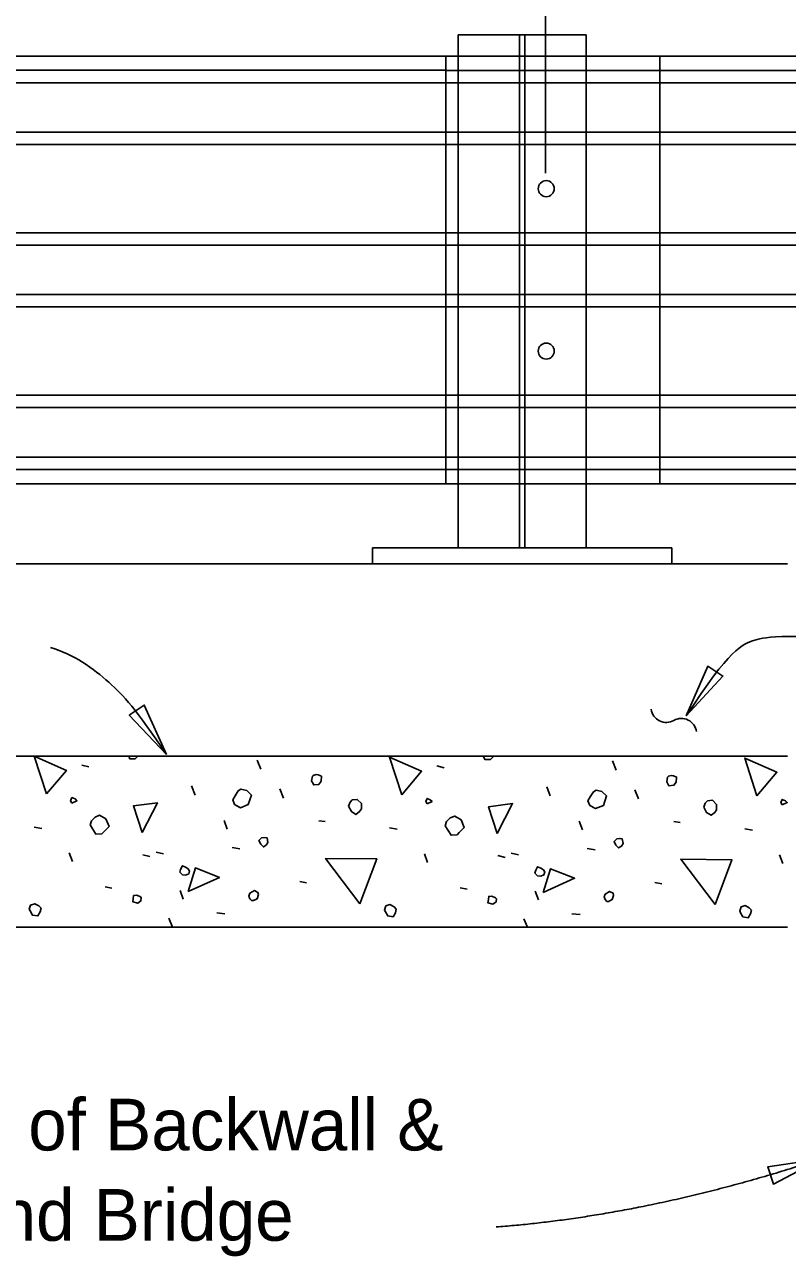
# Model space of a CAD drawing. Extents: x 0 to 41.1, y 0 to 25.9.
# Drawn here: x 24.589 to 27.563, y 5.17 to 9.971 of the extents above; entities that cross this region are included whole.
import ezdxf

# ---------------------------------------------------------------- set-up
doc = ezdxf.new("R2010")
doc.units = 0
for name, color, linetype in [('Dimension', 7, 'Continuous'), ('ExistSuperStruct', 7, 'Continuous'), ('Miscellaneous', 7, 'Continuous'), ('SteelMisc', 7, 'Continuous'), ('SteelMisc_h', 7, 'Continuous')]:
    doc.layers.add(name, color=color, linetype=linetype)

msp = doc.modelspace()

# ---------------------------------------------------------------- linework, layer by layer
at = {"layer": 'Dimension'}
for points in [[(27.168, 7.2761), (27.2522, 7.4698), (27.3113, 7.4313)], [(25.1421, 7.1256), (25.0556, 7.3183), (24.9969, 7.2791)], [(27.6953, 5.5504), (27.4865, 5.5185), (27.5086, 5.4515)]]:
    msp.add_lwpolyline(points, close=True, dxfattribs=at)
for centre, start, end in [((27.0905, 7.3104), 187.9536, 299.6808), ((27.1496, 7.2068), 7.9536, 119.6808)]:
    msp.add_arc(centre, 0.0596, start, end, dxfattribs=at)
for points, degree in [([(28.0581, 7.5636), (27.5366, 7.5973), (27.4332, 7.5751), (27.3392, 7.5386), (27.1681, 7.276)], 3), ([(24.6899, 7.5424), (24.7811, 7.5179), (24.9336, 7.4026), (25.0214, 7.3059), (25.1421, 7.1255)], 3), ([(27.6953, 5.5504), (27.0315, 5.3308), (26.4276, 5.2844)], 2)]:
    msp.add_open_spline(points, degree=degree, dxfattribs=at)
at = {"layer": 'ExistSuperStruct'}
for p, q in [((19.779, 7.8689), (27.5627, 7.8689)), ((27.5627, 7.1189), (19.779, 7.1189)), ((19.779, 6.4523), (27.5627, 6.4523))]:
    msp.add_line(p, q, dxfattribs=at)
at = {"layer": 'Miscellaneous'}
for p, q in [((26.6203, 9.392), (26.6203, 13.4579)), ((26.2319, 9.848), (26.2319, 8.1814)), ((27.0652, 9.848), (27.0652, 8.1814)), ((26.2319, 9.7925), (37.5468, 9.7925)), ((26.2319, 9.7443), (37.5468, 9.7443)), ((26.2319, 9.5515), (37.5468, 9.5515)), ((26.2319, 9.5032), (37.5468, 9.5032)), ((26.2319, 9.1593), (37.5468, 9.1593)), ((26.2319, 9.1111), (37.5468, 9.1111)), ((26.2319, 8.9182), (37.5468, 8.9182)), ((26.2319, 8.8701), (37.5468, 8.8701)), ((26.2319, 8.5262), (37.5468, 8.5262)), ((26.2319, 8.4779), (37.5468, 8.4779)), ((26.2319, 8.2851), (37.5468, 8.2851)), ((26.2319, 8.2369), (37.5468, 8.2369)), ((24.8119, 7.0847), (24.8402, 7.0776)), ((25.5102, 7.0688), (25.4961, 7.1042)), ((26.1966, 7.0812), (26.2249, 7.0741)), ((26.8949, 7.0653), (26.8807, 7.1006)), ((25.2539, 6.968), (25.2397, 7.0034)), ((25.598, 6.9563), (25.5838, 6.9916)), ((26.6386, 6.9645), (26.6244, 6.9999)), ((26.9827, 6.9528), (26.9685, 6.9881)), ((25.3794, 6.8355), (25.367, 6.869)), ((25.7359, 6.8679), (25.7606, 6.8644)), ((26.7641, 6.8319), (26.7517, 6.8655)), ((24.627, 6.8431), (24.657, 6.8378)), ((26.0116, 6.8396), (26.0417, 6.8343)), ((27.1205, 6.8644), (27.1453, 6.8608)), ((27.3963, 6.8361), (27.4264, 6.8308)), ((24.7754, 6.7088), (24.7631, 6.7424)), ((25.0495, 6.7353), (25.0777, 6.7282)), ((25.1019, 6.7453), (25.1301, 6.7382)), ((25.3982, 6.7636), (25.4283, 6.7583)), ((26.1601, 6.7053), (26.1478, 6.7389)), ((26.4341, 6.7318), (26.4624, 6.7247)), ((26.4865, 6.7418), (26.5148, 6.7347)), ((26.7829, 6.7601), (26.8129, 6.7548)), ((27.5448, 6.7017), (27.5324, 6.7353)), ((25.6616, 6.631), (25.6881, 6.6257)), ((27.0463, 6.6275), (27.0728, 6.6222)), ((24.9027, 6.6098), (24.9292, 6.6045)), ((25.2079, 6.5627), (25.1956, 6.5963)), ((26.2874, 6.6063), (26.3139, 6.601)), ((26.5926, 6.5592), (26.5802, 6.5928)), ((25.1655, 6.4531), (25.1514, 6.4885)), ((25.3381, 6.509), (25.3699, 6.5055)), ((26.5491, 6.4523), (26.536, 6.4849)), ((26.7228, 6.5055), (26.7546, 6.502))]:
    msp.add_line(p, q, dxfattribs=at)
for points in [[(24.6747, 6.9722), (24.627, 7.1189), (24.7525, 7.0641), (24.6747, 6.9722)], [(24.9953, 7.1189), (24.9993, 7.1095), (24.9958, 7.113)], [(24.9993, 7.1095), (25.0205, 7.1095), (25.03, 7.1189)], [(26.0594, 6.9687), (26.0116, 7.1154), (26.1371, 7.0606), (26.0594, 6.9687)], [(26.3791, 7.1189), (26.3787, 7.1183), (26.384, 7.1059), (26.3805, 7.1095)], [(26.384, 7.1059), (26.4052, 7.1059), (26.4158, 7.1165), (26.4152, 7.1189)], [(27.444, 6.9651), (27.3963, 7.1118), (27.5218, 7.057), (27.444, 6.9651)], [(25.7076, 7.0235), (25.7164, 7.0076), (25.7359, 7.0093), (25.7447, 7.0217), (25.7465, 7.0411), (25.7341, 7.0464), (25.7253, 7.0482), (25.7146, 7.0447), (25.7111, 7.0411), (25.7076, 7.0235)], [(27.0923, 7.0199), (27.1011, 7.004), (27.1205, 7.0058), (27.1294, 7.0182), (27.1311, 7.0376), (27.1188, 7.0429), (27.1099, 7.0447), (27.0993, 7.0411), (27.0958, 7.0376), (27.0923, 7.0199)], [(25.4077, 6.9309), (25.4307, 6.9185), (25.4607, 6.9309), (25.4731, 6.968), (25.4554, 6.9857), (25.4324, 6.991), (25.4218, 6.9839), (25.4095, 6.9645), (25.4006, 6.9486), (25.4077, 6.9309)], [(26.7924, 6.9274), (26.8153, 6.915), (26.8454, 6.9274), (26.8578, 6.9645), (26.8401, 6.9822), (26.8171, 6.9875), (26.8065, 6.9804), (26.7941, 6.961), (26.7853, 6.9451), (26.7924, 6.9274)], [(24.7737, 6.9368), (24.7931, 6.9457), (24.7861, 6.9528), (24.7737, 6.9581), (24.7684, 6.9457), (24.7737, 6.9368)], [(25.0471, 6.8213), (25.0135, 6.9256), (25.1072, 6.938), (25.0471, 6.8213)], [(25.8525, 6.9245), (25.8631, 6.9033), (25.8808, 6.8926), (25.895, 6.9033), (25.902, 6.9139), (25.902, 6.9351), (25.8861, 6.951), (25.8667, 6.9492), (25.8578, 6.9404), (25.8525, 6.9245)], [(26.1584, 6.9333), (26.1778, 6.9421), (26.1707, 6.9492), (26.1584, 6.9545), (26.1531, 6.9421), (26.1584, 6.9333)], [(26.4317, 6.8178), (26.3981, 6.9221), (26.4918, 6.9344), (26.4317, 6.8178)], [(27.2372, 6.9209), (27.2478, 6.8997), (27.2655, 6.8891), (27.2796, 6.8997), (27.2867, 6.9103), (27.2867, 6.9315), (27.2708, 6.9474), (27.2514, 6.9457), (27.2425, 6.9368), (27.2372, 6.9209)], [(27.543, 6.9298), (27.5625, 6.9386), (27.5554, 6.9457), (27.543, 6.951), (27.5377, 6.9386), (27.543, 6.9298)], [(24.8444, 6.852), (24.8674, 6.8149), (24.8904, 6.8166), (24.8992, 6.8255), (24.9186, 6.8449), (24.9063, 6.875), (24.8815, 6.8891), (24.8638, 6.882), (24.8497, 6.8679), (24.8444, 6.852)], [(26.2291, 6.8485), (26.252, 6.8113), (26.275, 6.8131), (26.2839, 6.8219), (26.3033, 6.8414), (26.2909, 6.8714), (26.2662, 6.8856), (26.2485, 6.8785), (26.2344, 6.8644), (26.2291, 6.8485)], [(25.5096, 6.776), (25.5202, 6.7654), (25.5308, 6.7724), (25.5379, 6.783), (25.5343, 6.8007), (25.5255, 6.8025), (25.5131, 6.8007), (25.5025, 6.7901), (25.5096, 6.776)], [(26.8943, 6.7724), (26.9049, 6.7618), (26.9155, 6.7689), (26.9225, 6.7795), (26.919, 6.7972), (26.9102, 6.799), (26.8978, 6.7972), (26.8872, 6.7866), (26.8943, 6.7724)], [(25.8967, 6.5444), (25.7624, 6.7212), (25.9621, 6.7194), (25.8967, 6.5444)], [(25.2044, 6.6569), (25.2168, 6.6551), (25.2291, 6.6604), (25.2327, 6.671), (25.2274, 6.6799), (25.2168, 6.687), (25.2044, 6.6923), (25.1973, 6.6781), (25.1938, 6.6675), (25.2044, 6.6569)], [(25.2267, 6.5921), (25.255, 6.6841), (25.3487, 6.6469), (25.2267, 6.5921)], [(26.5891, 6.6534), (26.6014, 6.6516), (26.6138, 6.6569), (26.6174, 6.6675), (26.612, 6.6764), (26.6014, 6.6834), (26.5891, 6.6887), (26.582, 6.6746), (26.5785, 6.664), (26.5891, 6.6534)], [(26.6114, 6.5886), (26.6397, 6.6805), (26.7334, 6.6434), (26.6114, 6.5886)], [(27.2814, 6.5409), (27.1471, 6.7176), (27.3468, 6.7159), (27.2814, 6.5409)], [(25.0106, 6.5515), (25.03, 6.5462), (25.0424, 6.555), (25.0441, 6.5674), (25.0406, 6.5709), (25.0265, 6.578), (25.0141, 6.5762), (25.0123, 6.5638), (25.0106, 6.5515)], [(25.4742, 6.5568), (25.4813, 6.5568), (25.4954, 6.5638), (25.5007, 6.5798), (25.499, 6.5886), (25.4848, 6.5957), (25.4672, 6.5851), (25.4636, 6.5744), (25.4672, 6.5638), (25.4742, 6.5568)], [(26.8589, 6.5532), (26.866, 6.5532), (26.8801, 6.5603), (26.8854, 6.5762), (26.8837, 6.5851), (26.8695, 6.5921), (26.8518, 6.5815), (26.8483, 6.5709), (26.8518, 6.5603), (26.8589, 6.5532)], [(24.611, 6.5161), (24.6199, 6.5002), (24.6411, 6.4967), (24.6499, 6.5126), (24.6535, 6.5267), (24.6446, 6.5356), (24.6287, 6.5444), (24.6128, 6.5391), (24.6075, 6.5232), (24.611, 6.5161)], [(25.9957, 6.5126), (26.0046, 6.4967), (26.0258, 6.4931), (26.0346, 6.509), (26.0381, 6.5232), (26.0293, 6.532), (26.0134, 6.5409), (25.9975, 6.5356), (25.9922, 6.5196), (25.9957, 6.5126)], [(26.3952, 6.5479), (26.4147, 6.5426), (26.4271, 6.5515), (26.4288, 6.5638), (26.4253, 6.5674), (26.4111, 6.5744), (26.3988, 6.5727), (26.397, 6.5603), (26.3952, 6.5479)], [(27.3804, 6.509), (27.3892, 6.4931), (27.4105, 6.4896), (27.4193, 6.5055), (27.4228, 6.5196), (27.414, 6.5285), (27.3981, 6.5373), (27.3822, 6.532), (27.3769, 6.5161), (27.3804, 6.509)]]:
    msp.add_lwpolyline(points, dxfattribs=at)
at = {"layer": 'SteelMisc'}
for p, q in [((26.279, 9.9314), (26.779, 9.9314)), ((26.279, 9.9314), (26.279, 9.8481)), ((26.779, 9.9314), (26.779, 9.848)), ((26.2319, 9.8481), (19.779, 9.8481)), ((19.779, 9.7926), (26.2319, 9.7926)), ((19.779, 9.7444), (26.2319, 9.7444)), ((19.779, 9.5515), (26.2319, 9.5515)), ((19.779, 9.5033), (26.2319, 9.5033)), ((19.779, 9.1594), (26.2319, 9.1594)), ((19.779, 9.1111), (26.2319, 9.1111)), ((19.779, 8.9183), (26.2319, 8.9183)), ((19.779, 8.8702), (26.2319, 8.8702)), ((19.779, 8.5262), (26.2319, 8.5262)), ((19.779, 8.478), (26.2319, 8.478)), ((19.779, 8.2852), (26.2319, 8.2852)), ((19.779, 8.237), (26.2319, 8.237)), ((26.2319, 8.1814), (19.779, 8.1814)), ((26.279, 8.1814), (26.279, 7.9314)), ((26.779, 8.1814), (26.779, 7.9314)), ((25.9457, 7.9314), (27.1124, 7.9314)), ((25.9457, 7.8689), (25.9457, 7.9314)), ((26.279, 7.9314), (26.779, 7.9314)), ((27.1124, 7.9314), (27.1124, 7.8689)), ((25.9457, 7.8689), (27.1124, 7.8689))]:
    msp.add_line(p, q, dxfattribs=at)
for centre in [(26.6228, 9.3313), (26.6228, 8.6982)]:
    msp.add_circle(centre, 0.0312, dxfattribs=at)
at = {"layer": 'SteelMisc_h'}
for p, q in [((26.5186, 7.9314), (26.5186, 9.9314)), ((26.5395, 7.9314), (26.5395, 9.9314)), ((37.5468, 9.848), (26.2319, 9.848)), ((26.279, 9.848), (26.279, 8.1814)), ((26.779, 9.848), (26.779, 8.1814)), ((37.5468, 8.1814), (26.2319, 8.1814))]:
    msp.add_line(p, q, dxfattribs=at)

# ---------------------------------------------------------------- texts
at = {"layer": 'Dimension'}
for s, p in [('Front Face of Backwall &', (23.2251, 5.5827)), ('Begin or End Bridge', (23.2251, 5.2307))]:
    msp.add_text(s, height=0.2016, dxfattribs=at).set_placement(p)

doc.saveas('drawing.dxf')
